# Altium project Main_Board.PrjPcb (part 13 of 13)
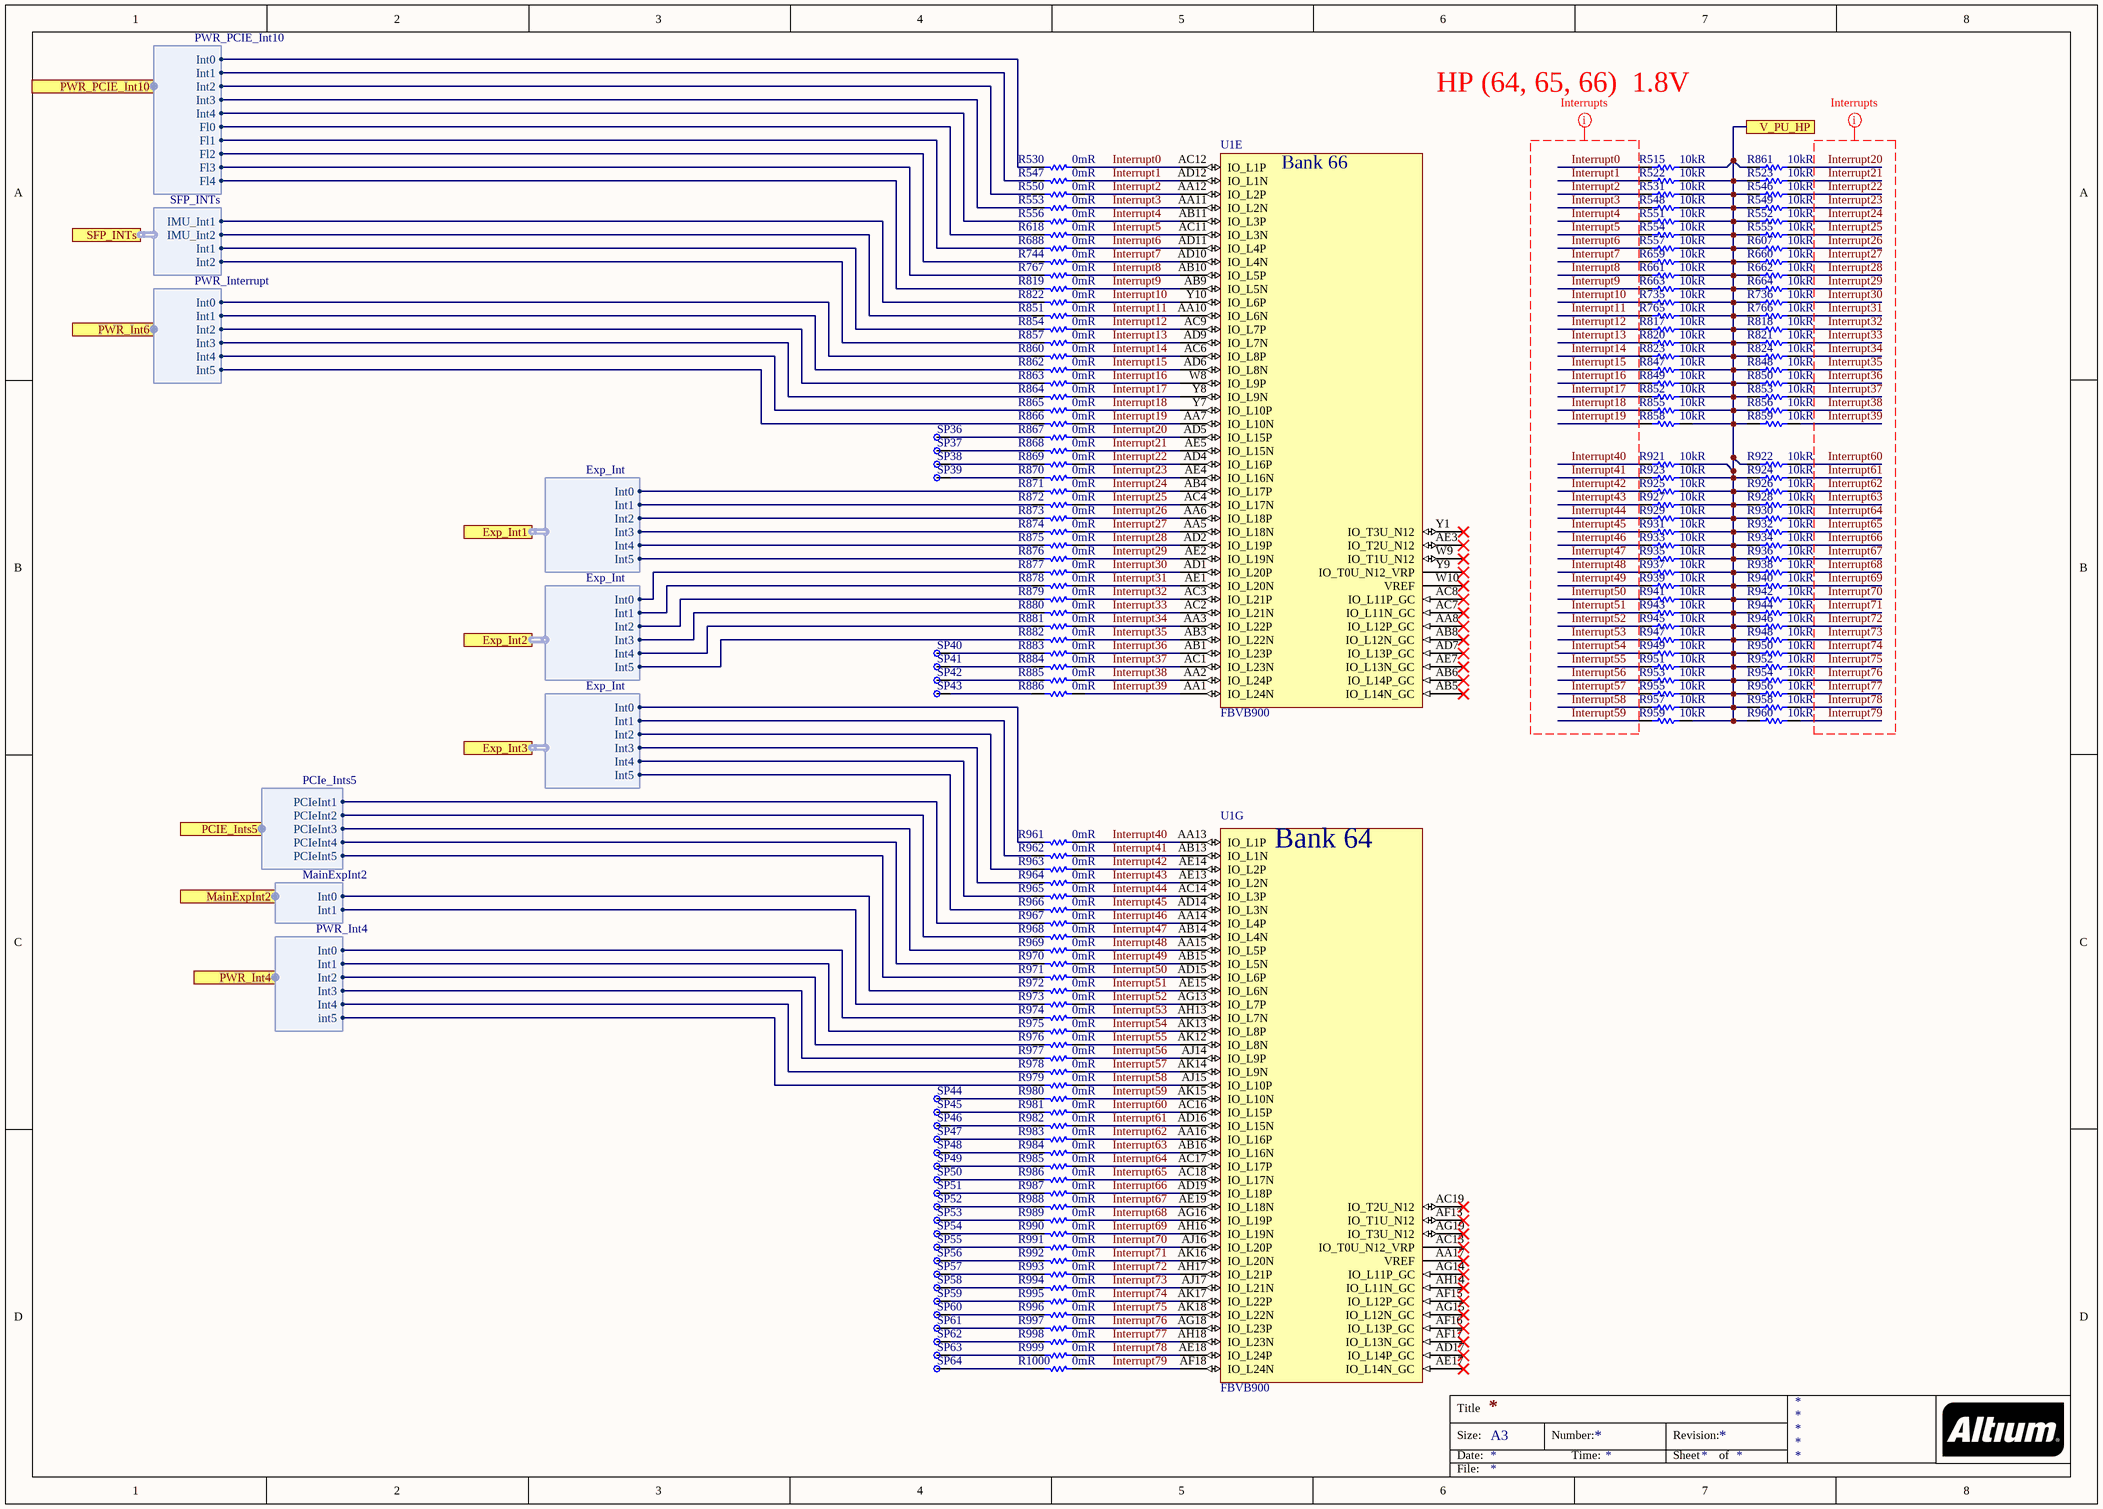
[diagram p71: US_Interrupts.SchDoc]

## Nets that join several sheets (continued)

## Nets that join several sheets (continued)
NetR760_2: Expander_RESET (R760.2 R761.1), U_Expander_RESET/I2C_Expander_Main_Rst (U35_I2C_Expander_Main_Rst.12)
NetR762_2: Expander_RESET (R762.2 R763.1), U_Expander_RESET/I2C_Expander_Main_Rst (U35_I2C_Expander_Main_Rst.11)
NetR860_2: PowerDistribition/HiCurrent/U_Pomiar_pradu_napiecia_3 (U64_U_Pomiar_pradu_napiecia_3.3), US_Interrupts (R860.2)
NetR862_2: PowerDistribition/HiCurrent/U_Pomiar_pradu_napiecia_4 (U64_U_Pomiar_pradu_napiecia_4.3), US_Interrupts (R862.2)
NetR863_2: PowerDistribition/HiCurrent/U_Pomiar_pradu_napiecia_5 (U64_U_Pomiar_pradu_napiecia_5.3), US_Interrupts (R863.2)
NetR864_2: PowerDistribition/HiCurrent/U_Pomiar_pradu_napiecia_6 (U64_U_Pomiar_pradu_napiecia_6.3), US_Interrupts (R864.2)
NetR865_2: Power_Hi_Curr (U18.A3), US_Interrupts (R865.2)
NetR866_2: Pomiar_napiecia_high_curr (U72.3), US_Interrupts (R866.2)
NetR918_2: Ultrascale+_02 (R918.2), Trans_LS_I2C0 (U36_Trans_LS_I2C0.8)
NetR919_2: Ultrascale+_02 (R919.2), Trans_LS_I2C1 (U36_Trans_LS_I2C1.8)
NetSP12_I2C_Bridge_GPIO_1: Ext_GPIO/I2C_Bridge_GPIO (SP12_I2C_Bridge_GPIO.1 U3_I2C_Bridge_GPIO.24), U_Expander_RESET/I2C_Expander_Main_Rst (U35_I2C_Expander_Main_Rst.3)
NetU24_SPI_bridge_Main_12: HighSpeed/SPI_bridge_PCIe (5 pins), SPI_bridge_Main (U24_SPI_bridge_Main.12)
NetU24_SPI_bridge_Main_13: HighSpeed/SPI_bridge_PCIe (5 pins), SPI_bridge_Main (U24_SPI_bridge_Main.13)
NetU24_SPI_bridge_Main_14: HighSpeed/SPI_bridge_PCIe (5 pins), SPI_bridge_Main (U24_SPI_bridge_Main.14)
NVMe_Rx_0_N: Sata (J27.47 R541.2), GTR (C677.2)
NVMe_Rx_0_P: Sata (J27.49 R541.1), GTR (C653.2)
NVMe_Rx_1_N: Sata (J27.35 R542.1), GTR (C716.2)
NVMe_Rx_1_P: Sata (J27.37 R542.2), GTR (C715.2)
NVMe_Tx_0_N: Sata (J27.41), GTR (C651.2)
NVMe_Tx_0_P: Sata (J27.43), GTR (C649.2)
NVMe_Tx_1_N: Sata (J27.29), GTR (C718.2)
NVMe_Tx_1_P: Sata (J27.31), GTR (C717.2)
OSC_500Out: System_CLK (TP20.1), DAC (X2.10), CLK_Mux (C333.1)
P4HS_PowerAlert_Pcie0: HighSpeed/Power4HighSpeed/U_Pomiar_pradu_napiecia_PCIe0 (U64_U_Pomiar_pradu_napiecia_PCIe0.3), US_Interrupts (R530.2)
P4HS_PowerAlert_Pcie1: HighSpeed/Power4HighSpeed/U_Pomiar_pradu_napiecia_PCIe1 (U64_U_Pomiar_pradu_napiecia_PCIe1.3), US_Interrupts (R547.2)
P4HS_PowerAlert_Pcie2: HighSpeed/Power4HighSpeed/U_Pomiar_pradu_napiecia_PCIe2 (U64_U_Pomiar_pradu_napiecia_PCIe2.3), US_Interrupts (R550.2)
P4HS_PowerAlert_Pcie3: HighSpeed/Power4HighSpeed/U_Pomiar_pradu_napiecia_PCIe3 (U64_U_Pomiar_pradu_napiecia_PCIe3.3), US_Interrupts (R553.2)
P4HS_PowerAlert_Pcie4: HighSpeed/Power4HighSpeed/U_Pomiar_pradu_napiecia_PCIe4 (U64_U_Pomiar_pradu_napiecia_PCIe4.3), US_Interrupts (R556.2)
PCIe_RESET: Ultrascale+_01 (R788.1 TP35.1), Sata (J27.50)
PG1_1: Power_Distribution (R835.1), Power_ADP1850_Dual (R295.2 U37.27)
PG1_2: Power_Distribution (R838.1), Power_ADP1850_Dual_1 (R313.2 U38.27)
PG1_TPS7A8801: TPS7A88_5V_Dual_3.3V_3.3V (R440.2 U61.17), PowerDistribition/Zasilanie CLK/I2C_Expander_PWR_CLK (U35_I2C_Expander_PWR_CLK.28)
PG2_2: Power_Distribution (R836.1), Power_ADP1850_Dual_1 (R314.2 U38.14)
PG2_TPS7A8801: TPS7A88_5V_Dual_3.3V_3.3V (R441.2 U61.9), PowerDistribition/Zasilanie CLK/I2C_Expander_PWR_CLK (U35_I2C_Expander_PWR_CLK.1)
PG2_TPS7A8801_0V9: Power_ADP1850_Dual (U37.8), TPS7A88_3V3_1V8_0V9V@2x1A (R676.2 U70.9), ST1L08_5V_0V6 (U73.5), Power_LED (T33.1)
PG_2V5@1.5A: Power_Hi_Curr (U18.A2), Power_Ethernet (R392.1 U49.5), Power_LED (T38.1)
PG_3V3@14A_EXP: Power_Distribution (R835.2 R837.1), PowerDistribition/I2C_Expander_PWR_Dist (U35_I2C_Expander_PWR_Dist.25), Power_LED (T37.1)
PG_5V@10A_EXP: Power_Distribution (R836.2 R839.1), PowerDistribition/I2C_Expander_PWR_Dist (U35_I2C_Expander_PWR_Dist.26), Power_LED (T41.1)
PG_12@8A_EXP: Power_Distribution (R838.2 R840.1), PowerDistribition/I2C_Expander_PWR_Dist (U35_I2C_Expander_PWR_Dist.27), Power_LED (T45.1)
PG_48_20V: PowerDistribition/I2C_Expander_PWR_Dist (U35_I2C_Expander_PWR_Dist.4), Power_48_20V@3A (U65.19), Power_LED (T49.1), GPIO_I2C (R828.2)
PG_ADP1850_1V2_REG4: ADP1741_3V3_0V85 (R435.1 R668.1 U69.4), Power_LED (T40.1)
PG_LT3042: LT3042_12V_5V_LNLDO (R442.1 U62.4), PowerDistribition/Zasilanie CLK/I2C_Expander_PWR_CLK (U35_I2C_Expander_PWR_CLK.25), Power_LED (R1082.1)
PG_PS_LTC6952_1: PowerDistribition/Zasilanie CLK/5to3V3_1 (R431_5to3V3_1.1 U59_5to3V3_1.5), PowerDistribition/Zasilanie CLK/I2C_Expander_PWR_CLK (U35_I2C_Expander_PWR_CLK.17), Power_LED (T32.1)
PG_PS_LTC6952_2: PowerDistribition/Zasilanie CLK/5to3V3_2 (R431_5to3V3_2.1 U59_5to3V3_2.5), PowerDistribition/Zasilanie CLK/I2C_Expander_PWR_CLK (U35_I2C_Expander_PWR_CLK.21), Power_LED (T47.1)
PGND: Power_48_20V@3A (17 pins), RJ45 (D3.2 D4.2 R324.1)
Power1_In: Power_Distribution (P8.1), PowerDistribition/U_Pomiar_pradu_napiecia_1 (R448_U_Pomiar_pradu_napiecia_1.1 U64_U_Pomiar_pradu_napiecia_1.10)
Power1_In_CM: Power_Switch (9 pins), PowerDistribition/U_Pomiar_pradu_napiecia_1 (R448_U_Pomiar_pradu_napiecia_1.2 U64_U_Pomiar_pradu_napiecia_1.8 U64_U_Pomiar_pradu_napiecia_1.9)
Power2_In: Power_Distribution (P10.1), PowerDistribition/U_Pomiar_pradu_napiecia_2 (R448_U_Pomiar_pradu_napiecia_2.1 U64_U_Pomiar_pradu_napiecia_2.10)
Power2_In_CM: Power_Switch (9 pins), PowerDistribition/U_Pomiar_pradu_napiecia_2 (R448_U_Pomiar_pradu_napiecia_2.2 U64_U_Pomiar_pradu_napiecia_2.8 U64_U_Pomiar_pradu_napiecia_2.9)
Power_3.3_1: Zasilanie_CLKDistribution (20 pins), TPS7A88_5V_Dual_3.3V_3.3V (6 pins)
Power_3.3_2: Zasilanie_CLKDistribution (10 pins), TPS7A88_5V_Dual_3.3V_3.3V (6 pins)
Power_MUX_Status0: Power_Switch (R630.2 U5.9), PowerDistribition/I2C_Expander_PWR_Dist (U35_I2C_Expander_PWR_Dist.22)
Power_MUX_Status1: Power_Switch (R11.1 U4.9), PowerDistribition/I2C_Expander_PWR_Dist (U35_I2C_Expander_PWR_Dist.23)
Power_MUX_Status2: Power_Switch (R13.2 U48.9), PowerDistribition/I2C_Expander_PWR_Dist (U35_I2C_Expander_PWR_Dist.24)
PS_MODE1: PS_Config (P2.3 R350.1 S1.2 U1.R19), USB3 (U74.2)
PS_POR: PS_Config (P3.2 R355.2 U1.N19), RJ45 (U76.1), FTDI (U77.6), USB3 (U74.1)
PS_Reset: PS_Config (P4.1 R354.1 U1.P20), FTDI (U77.4 U78.6)
PWR_ExtIO_INT0: PowerDistribition/I2C_Expander_PWR_Dist (U35_I2C_Expander_PWR_Dist.16), US_Interrupts (R977.2)
PWR_ExtIO_INT1: PowerDistribition/I2C_Expander_PWR_Dist (U35_I2C_Expander_PWR_Dist.15), US_Interrupts (R976.2)
PWR_ExtIO_INT2: PowerDistribition/Zasilanie CLK/I2C_Expander_PWR_CLK (U35_I2C_Expander_PWR_CLK.15), US_Interrupts (R978.2)
PWR_ExtIO_INT3: PowerDistribition/Zasilanie CLK/I2C_Expander_PWR_CLK (U35_I2C_Expander_PWR_CLK.16), US_Interrupts (R979.2)
PWR_ExtIO_nReset: PowerDistribition/I2C_Expander_PWR_Dist (U35_I2C_Expander_PWR_Dist.14), Expander_RESET (R755.1), U_Expander_RESET/I2C_Expander_Main_Rst (U35_I2C_Expander_Main_Rst.27)
PWR_OUT_20V: Power_Switch (18 pins), Power_Hi_Curr (R266.2), HI_Curr_ADP1850 (29 pins), Power_ADP1850_Dual (21 pins), Power_ADP1850_Dual_1 (21 pins)
PWR_PowerAlert0: PowerDistribition/I2C_Expander_PWR_Dist (U35_I2C_Expander_PWR_Dist.17), PowerDistribition/U_Pomiar_pradu_napiecia_1 (U64_U_Pomiar_pradu_napiecia_1.3), US_Interrupts (R974.2)
PWR_PowerAlert1: PowerDistribition/I2C_Expander_PWR_Dist (U35_I2C_Expander_PWR_Dist.18), PowerDistribition/U_Pomiar_pradu_napiecia_2 (U64_U_Pomiar_pradu_napiecia_2.3), US_Interrupts (R975.2)
PWR_Switch1_En: Power_Switch (U6.A2), PowerDistribition/I2C_Expander_PWR_Dist (U35_I2C_Expander_PWR_Dist.28)
PWR_Switch1_Flag: Power_Switch (R29.1 U6.A3), PowerDistribition/I2C_Expander_PWR_Dist (U35_I2C_Expander_PWR_Dist.1)
PWR_Switch2_En: Power_Switch (U7.A2), PowerDistribition/I2C_Expander_PWR_Dist (U35_I2C_Expander_PWR_Dist.2)
PWR_Switch2_Flag: Power_Switch (R30.1 U7.A3), PowerDistribition/I2C_Expander_PWR_Dist (U35_I2C_Expander_PWR_Dist.3)
RAM_DDR4_VTT: RAM (25 pins), ST1L08_5V_0V6 (C722.2 C723.2 R689.1 U73.8)
RAM_Vcc1V2: Power_ADP1850_Dual (R297.1), PowerDistribition/HiCurrent/U_Pomiar_pradu_napiecia_4 (R448_U_Pomiar_pradu_napiecia_4.2 U64_U_Pomiar_pradu_napiecia_4.8 U64_U_Pomiar_pradu_napiecia_4.9), RAM_Power (128 pins), XilinxPower (16 pins), FPGA_Decoupling (C741.2 C760.1 C761.2), RAM (C36.2 R58.2)
RF_SYSREF_TO_FPGA_N: Ultrascale+_02 (U1.AK11), HighSpeed/PCIE0 (J1_PCIE0.48)
RF_SYSREF_TO_FPGA_N: Ultrascale+_02 (U1.AG10), HighSpeed/PCIE1 (J1_PCIE1.48)
RF_SYSREF_TO_FPGA_N: Ultrascale+_02 (U1.AH9), HighSpeed/PCIE2 (J1_PCIE2.48)
RF_SYSREF_TO_FPGA_N: Ultrascale+_02 (U1.AE9), HighSpeed/PCIE3 (J1_PCIE3.48)
RF_SYSREF_TO_FPGA_N: Ultrascale+_02 (U1.AK5), HighSpeed/PCIE4 (J1_PCIE4.48)
RF_SYSREF_TO_FPGA_P: Ultrascale+_02 (U1.AJ11), HighSpeed/PCIE0 (J1_PCIE0.50)
RF_SYSREF_TO_FPGA_P: Ultrascale+_02 (U1.AF10), HighSpeed/PCIE1 (J1_PCIE1.50)
RF_SYSREF_TO_FPGA_P: Ultrascale+_02 (U1.AJ9), HighSpeed/PCIE2 (J1_PCIE2.50)
RF_SYSREF_TO_FPGA_P: Ultrascale+_02 (U1.AE8), HighSpeed/PCIE3 (J1_PCIE3.50)
RF_SYSREF_TO_FPGA_P: Ultrascale+_02 (U1.AJ5), HighSpeed/PCIE4 (J1_PCIE4.50)
RST_brigde: SFP_Group+IMU/I2C_Bridge_SFP (SP12_I2C_Bridge_SFP.1 U3_I2C_Bridge_SFP.24), Expander_RESET (R757.1), U_Expander_RESET/I2C_Expander_Main_Rst (U35_I2C_Expander_Main_Rst.1)
SetClk_Si53323_2: CLK_Mux (T36.1), Ultrascale+_02 (R900.2)
SFP0_LOS: SFP (J32.8 R66.1), SFP_Group+IMU/I2C_Expander_SFP (U35_I2C_Expander_SFP.4)
SFP0_Rx_N: SFP (J32.19), bank226 (C57#2.2 R706#2.2)
SFP0_Rx_P: SFP (J32.18), bank226 (C57#2.1 R705#2.2)
SFP0_Tx_N: SFP (J32.12), bank226 (C42.2 R704#2.2)
SFP0_Tx_P: SFP (J32.13), bank226 (C42.1 R703#2.2)
SFP0_TxDis: SFP (J32.3 R68.1), SFP_Group+IMU/I2C_Expander_SFP (U35_I2C_Expander_SFP.3)
SFP0_TxF: SFP (J32.2 R67.1), SFP_Group+IMU/I2C_Expander_SFP (U35_I2C_Expander_SFP.2)
SFP1_LOS: SFP1 (J33.8 R136.1), SFP_Group+IMU/I2C_Expander_SFP (U35_I2C_Expander_SFP.24)
SFP1_Rx_N: SFP1 (J33.19), bank226 (C68#2.2 R830#2.2)
SFP1_Rx_P: SFP1 (J33.18), bank226 (C68#2.1 R829#2.2)
SFP1_Tx_N: SFP1 (J33.12), bank226 (C58#2.2 R708#2.2)
SFP1_Tx_P: SFP1 (J33.13), bank226 (C58#2.1 R707#2.2)
SFP1_TxDis: SFP1 (J33.3 R138.1), SFP_Group+IMU/I2C_Expander_SFP (U35_I2C_Expander_SFP.23)
SFP1_TxF: SFP1 (J33.2 R137.1), SFP_Group+IMU/I2C_Expander_SFP (U35_I2C_Expander_SFP.22)
SFP2_LOS: SFP2 (J34.8 R146.1), SFP_Group+IMU/I2C_Expander_SFP (U35_I2C_Expander_SFP.27)
SFP2_Rx_N: SFP2 (J34.19), bank226 (C113#2.2 R834#2.2)
SFP2_Rx_P: SFP2 (J34.18), bank226 (C113#2.1 R833#2.2)
SFP2_Tx_N: SFP2 (J34.12), bank226 (C69#2.2 R832#2.2)
SFP2_Tx_P: SFP2 (J34.13), bank226 (C69#2.1 R831#2.2)
SFP2_TxDis: SFP2 (J34.3 R148.1), SFP_Group+IMU/I2C_Expander_SFP (U35_I2C_Expander_SFP.26)
SFP2_TxF: SFP2 (J34.2 R147.1), SFP_Group+IMU/I2C_Expander_SFP (U35_I2C_Expander_SFP.25)
SFP3_LOS: SFP3 (J35.8 R156.1), SFP_Group+IMU/I2C_Expander_SFP (U35_I2C_Expander_SFP.19)
SFP3_Rx_N: SFP3 (J35.19), bank226 (C117#2.2 R844#2.2)
SFP3_Rx_P: SFP3 (J35.18), bank226 (C117#2.1 R843#2.2)
SFP3_Tx_N: SFP3 (J35.12), bank226 (C114#2.2 R842#2.2)
SFP3_Tx_P: SFP3 (J35.13), bank226 (C114#2.1 R841#2.2)
SFP3_TxDis: SFP3 (J35.3 R158.1), SFP_Group+IMU/I2C_Expander_SFP (U35_I2C_Expander_SFP.18)
SFP3_TxF: SFP3 (J35.2 R157.1), SFP_Group+IMU/I2C_Expander_SFP (U35_I2C_Expander_SFP.17)
SFP_I2C4.SCL: WR_Clock (R130.2), SFP_Group+IMU/I2C_Bridge_SFP (R9_I2C_Bridge_SFP.2 SP11_I2C_Bridge_SFP.1 U3_I2C_Bridge_SFP.11), IMU (U58.13)
SFP_I2C4.SDA: WR_Clock (R131.2), SFP_Group+IMU/I2C_Bridge_SFP (R10_I2C_Bridge_SFP.2 SP10_I2C_Bridge_SFP.1 U3_I2C_Bridge_SFP.10), IMU (U58.14)
SFP_I2C5.SCL: Power_Distribution (R457.2 R465.2 R593.2 R597.2), Power_Hi_Curr (10 pins), PowerDistribition/HiCurrent/U_Pomiar_pradu_napiecia_3 (U64_U_Pomiar_pradu_napiecia_3.5), PowerDistribition/HiCurrent/U_Pomiar_pradu_napiecia_4 (U64_U_Pomiar_pradu_napiecia_4.5), PowerDistribition/HiCurrent/U_Pomiar_pradu_napiecia_5 (U64_U_Pomiar_pradu_napiecia_5.5), PowerDistribition/HiCurrent/U_Pomiar_pradu_napiecia_6 (U64_U_Pomiar_pradu_napiecia_6.5), Pomiar_napiecia_high_curr (U72.5), PowerDistribition/Zasilanie CLK/I2C_Expander_PWR_CLK (U35_I2C_Expander_PWR_CLK.8), PowerDistribition/I2C_Expander_PWR_Dist (U35_I2C_Expander_PWR_Dist.8), PowerDistribition/U_Pomiar_pradu_napiecia_1 (U64_U_Pomiar_pradu_napiecia_1.5), PowerDistribition/U_Pomiar_pradu_napiecia_2 (U64_U_Pomiar_pradu_napiecia_2.5), SFP_Group+IMU/I2C_Bridge_SFP (R7_I2C_Bridge_SFP.2 SP14_I2C_Bridge_SFP.1 U3_I2C_Bridge_SFP.13)
SFP_I2C5.SDA: Power_Distribution (R459.2 R466.2 R594.2 R598.2), Power_Hi_Curr (10 pins), PowerDistribition/HiCurrent/U_Pomiar_pradu_napiecia_3 (U64_U_Pomiar_pradu_napiecia_3.4), PowerDistribition/HiCurrent/U_Pomiar_pradu_napiecia_4 (U64_U_Pomiar_pradu_napiecia_4.4), PowerDistribition/HiCurrent/U_Pomiar_pradu_napiecia_5 (U64_U_Pomiar_pradu_napiecia_5.4), PowerDistribition/HiCurrent/U_Pomiar_pradu_napiecia_6 (U64_U_Pomiar_pradu_napiecia_6.4), Pomiar_napiecia_high_curr (U72.4), PowerDistribition/Zasilanie CLK/I2C_Expander_PWR_CLK (U35_I2C_Expander_PWR_CLK.9), PowerDistribition/I2C_Expander_PWR_Dist (U35_I2C_Expander_PWR_Dist.9), PowerDistribition/U_Pomiar_pradu_napiecia_1 (U64_U_Pomiar_pradu_napiecia_1.4), PowerDistribition/U_Pomiar_pradu_napiecia_2 (U64_U_Pomiar_pradu_napiecia_2.4), SFP_Group+IMU/I2C_Bridge_SFP (R8_I2C_Bridge_SFP.2 SP13_I2C_Bridge_SFP.1 U3_I2C_Bridge_SFP.12)
SFP_I2C6.SCL: HighSpeed/I2C_Bridge_PCIE (U3_I2C_Bridge_PCIE.19), SFP_Group+IMU/I2C_Bridge_SFP (R5_I2C_Bridge_SFP.2 SP16_I2C_Bridge_SFP.1 U3_I2C_Bridge_SFP.15)
SFP_I2C6.SDA: HighSpeed/I2C_Bridge_PCIE (U3_I2C_Bridge_PCIE.20), SFP_Group+IMU/I2C_Bridge_SFP (R6_I2C_Bridge_SFP.2 SP15_I2C_Bridge_SFP.1 U3_I2C_Bridge_SFP.14)
SFP_I2C7.SCL: SFP_Group+IMU/I2C_Bridge_SFP (R3_I2C_Bridge_SFP.2 SP18_I2C_Bridge_SFP.1 U3_I2C_Bridge_SFP.17), SFP_Group+IMU/I2C_Expander_SFP (U35_I2C_Expander_SFP.8)
SFP_I2C7.SDA: SFP_Group+IMU/I2C_Bridge_SFP (R4_I2C_Bridge_SFP.2 SP17_I2C_Bridge_SFP.1 U3_I2C_Bridge_SFP.16), SFP_Group+IMU/I2C_Expander_SFP (U35_I2C_Expander_SFP.9)
SFP_INT0: SFP_Group+IMU/I2C_Expander_SFP (U35_I2C_Expander_SFP.16), US_Interrupts (R854.2)
SFP_INT1: SFP_Group+IMU/I2C_Expander_SFP (U35_I2C_Expander_SFP.15), US_Interrupts (R857.2)
SFP_IO_nReset: SFP_Group+IMU/I2C_Expander_SFP (U35_I2C_Expander_SFP.14), Expander_RESET (R756.1), U_Expander_RESET/I2C_Expander_Main_Rst (U35_I2C_Expander_Main_Rst.28)
SGMI_C_Rx_N: RJ45 (C484.2), GTR (U1.G26)
SGMI_C_Rx_P: RJ45 (C483.2), GTR (U1.G25)
SGMI_C_Tx_N: RJ45 (C482.2), GTR (U1.G29)
SGMI_C_Tx_P: RJ45 (C479.2), GTR (U1.G30)
Si53323_1_Q2_LVDS_N: CLK_Mux (C725.1 R386.2 R387.2), Ultrascale+_02 (U1.AG3)
Si53323_1_Q2_LVDS_P: CLK_Mux (C724.1 R100.2 R125.2), Ultrascale+_02 (U1.AG4)
Si53323_2_Q1_N: CLK_Mux (U32.10), LTC6952 (C44.2 R79.2)
Si53323_2_Q1_P: CLK_Mux (U32.9), LTC6952 (C43.2 R76.1)
Si53323_2_Q2_LVDS_N: CLK_Mux (C727.1 R486.2 R487.2), Ultrascale+_02 (U1.A16)
Si53323_2_Q2_LVDS_P: CLK_Mux (C726.1 R427.2 R538.2), Ultrascale+_02 (U1.A17)
SPI1_CLK: Ultrascale+_01 (J25.1 R803.1), Ultrascale+_02 (U15.14), SPI_bridge_Main (5 pins)
SPI1_CS: Ultrascale+_01 (J25.4 R123.1 R806.1), Ultrascale+_02 (R124.1 U15.11), SPI_bridge_Main (5 pins)
SPI1_MISO: Ultrascale+_01 (J25.3 R807.1), Ultrascale+_02 (U15.13), SPI_bridge_Main (5 pins)
SPI1_MOSI: Ultrascale+_01 (J25.2 R808.1), Ultrascale+_02 (U15.12), SPI_bridge_Main (5 pins)
SPI_DAC_CS: DAC (U30.14), SPI_bridge_Main (R238_SPI_bridge_Main.1 SP27_SPI_bridge_Main.1 U27_SPI_bridge_Main.11)
SYNC_N: Ultrascale+_02 (U1.AK10), HighSpeed/PCIE0 (J1_PCIE0.12)
SYNC_N: Ultrascale+_02 (U1.AK8), HighSpeed/PCIE1 (J1_PCIE1.12)
SYNC_N: Ultrascale+_02 (U1.AF7), HighSpeed/PCIE2 (J1_PCIE2.12)
SYNC_N: Ultrascale+_02 (U1.AK6), HighSpeed/PCIE3 (J1_PCIE3.12)
SYNC_N: Ultrascale+_02 (U1.AK4), HighSpeed/PCIE4 (J1_PCIE4.12)
SYNC_P: Ultrascale+_02 (U1.AJ10), HighSpeed/PCIE0 (J1_PCIE0.14)
SYNC_P: Ultrascale+_02 (U1.AK9), HighSpeed/PCIE1 (J1_PCIE1.14)
SYNC_P: Ultrascale+_02 (U1.AF8), HighSpeed/PCIE2 (J1_PCIE2.14)
SYNC_P: Ultrascale+_02 (U1.AK7), HighSpeed/PCIE3 (J1_PCIE3.14)
SYNC_P: Ultrascale+_02 (U1.AJ4), HighSpeed/PCIE4 (J1_PCIE4.14)
uart0_RxD: Ultrascale+_01 (R779.1 TP32.1), FTDI (U57.12)
uart0_TxD: Ultrascale+_01 (R778.1 TP27.1), FTDI (U57.11)
uart1_RxD: Ultrascale+_01 (R776.1 TP31.1), FTDI (U57.13)
uart1_TxD: Ultrascale+_01 (R777.1 TP29.1), FTDI (U57.14)
US2_FTDI_UART1_RXD: Ultrascale+_02 (R910.2), FTDI (U79.13)
US2_FTDI_UART1_TXD: Ultrascale+_02 (R909.2), FTDI (U79.14)
US+_MGTVccAux: Ultrascale+_02 (7 pins), Power_Low_Curr (7 pins), XilinxPower (18 pins), FPGA_Decoupling (C756.2 C759.2), Trans_LS_I2C0 (U36_Trans_LS_I2C0.2), Trans_LS_I2C1 (U36_Trans_LS_I2C1.2), FTDI (U79.15), US_Interrupts (80 pins)
US+_Vcc_PS_Batt: XilinxPower (B1.1 R276.1 U1.U20), FPGA_Decoupling (C747.1 C748.2)
US+_Vcc_PS_DDR_504: Power_Low_Curr (9 pins), XilinxPower (7 pins), FPGA_Decoupling (C753.1 C754.2 C755.2)
US+_Vcc_PS_IntFp: HI_Curr_ADP1850 (R271.2), Pomiar_napiecia_high_curr (R617.2 U72.8 U72.9), XilinxPower (53 pins), FPGA_Decoupling (11 pins)
US_PS_JTAG_TCK: PS_Config (R346.2 U1.L19), FTDI (R1028.2)
US_PS_JTAG_TDI: PS_Config (R347.2 U1.L20), FTDI (R1026.2)
US_PS_JTAG_TDO: PS_Config (U1.M20), FTDI (R1029.2)
US_PS_JTAG_TMS: PS_Config (R348.2 U1.L21), FTDI (R1027.2)
USB2_CLK: Ultrascale+_01 (R362.2), USB3 (U45.1)
USB2_D0: Ultrascale+_01 (R116.2), USB3 (U45.3)
USB2_D1: Ultrascale+_01 (R117.2), USB3 (U45.4)
USB2_D2: Ultrascale+_01 (R115.2), USB3 (U45.5)
USB2_D3: Ultrascale+_01 (R119.2), USB3 (U45.6)
USB2_D4: Ultrascale+_01 (R120.2), USB3 (U45.7)
USB2_D5: Ultrascale+_01 (R121.2), USB3 (U45.9)
USB2_D6: Ultrascale+_01 (R122.2), USB3 (U45.10)
USB2_D7: Ultrascale+_01 (R802.1), USB3 (U45.13)
USB2_DIR: Ultrascale+_01 (R800.1), USB3 (U45.31)
USB2_NXT: Ultrascale+_01 (R801.1), USB3 (U45.2)
USB2_STP: Ultrascale+_01 (R118.2), USB3 (U45.29)
USB_RX_N: USB3 (C543.2), GTR (U1.J25)
USB_RX_P: USB3 (C542.2), GTR (U1.J26)
USB_TX_N: USB3 (C541.2), GTR (U1.H28)
USB_TX_P: USB3 (C540.2), GTR (U1.H27)
uSD_CD: Ultrascale+_01 (R782.1), uSD (R381.1 R845#2.2 U47.D3)
uSD_CLK: Ultrascale+_01 (R96.2 R97.1), uSD (U47.C1)
uSD_CMD: Ultrascale+_01 (R95.2), uSD (U47.D2)
uSD_D0: Ultrascale+_01 (R87.2), uSD (U47.D1)
uSD_D1: Ultrascale+_01 (R88.2), uSD (U47.E1)
uSD_D2: Ultrascale+_01 (R89.2), uSD (U47.A1)
uSD_D3: Ultrascale+_01 (R90.2), uSD (U47.B1)
uSD_D4: Ultrascale+_01 (R91.1), uSD (U47.B2)
uSD_D5: Ultrascale+_01 (R92.1), uSD (U47.A2)
uSD_D6: Ultrascale+_01 (R93.1), uSD (U47.A3)
uSD_D7: Ultrascale+_01 (R94.1), uSD (U47.E3)
V_PoE+: Power_48_20V@3A (6 pins), RJ45 (D3.1 D4.1 R324.2)
VDD_DIG: WR_Clock (7 pins), Zasilanie_CLKDistribution (C93.1 C165.2 FB21.2 U16.8)
Vout1_1: Power_ADP1850_Dual (13 pins), PowerDistribition/HiCurrent/U_Pomiar_pradu_napiecia_3 (R448_U_Pomiar_pradu_napiecia_3.1 U64_U_Pomiar_pradu_napiecia_3.10)
Vout1_2: Power_ADP1850_Dual_1 (13 pins), PowerDistribition/HiCurrent/U_Pomiar_pradu_napiecia_5 (R448_U_Pomiar_pradu_napiecia_5.1 U64_U_Pomiar_pradu_napiecia_5.10)
Vout2_1: Power_ADP1850_Dual (13 pins), PowerDistribition/HiCurrent/U_Pomiar_pradu_napiecia_4 (R448_U_Pomiar_pradu_napiecia_4.1 U64_U_Pomiar_pradu_napiecia_4.10)
Vout2_2: Power_ADP1850_Dual_1 (13 pins), PowerDistribition/HiCurrent/U_Pomiar_pradu_napiecia_6 (R448_U_Pomiar_pradu_napiecia_6.1 U64_U_Pomiar_pradu_napiecia_6.10)
WR_LMK_CLK_RC_HF1_N: WR_Clock (C729.2 R1086.1), Ultrascale+_02 (U1.AJ1)
WR_LMK_CLK_RC_HF1_P: WR_Clock (C729.1 R1085.1), Ultrascale+_02 (U1.AJ2)
WR_LMK_CLK_RC_HF2_N: WR_Clock (C730.2 R1088.1), Ultrascale+_02 (U1.C17)
WR_LMK_CLK_RC_HF2_P: WR_Clock (C730.1 R1087.1), Ultrascale+_02 (U1.B16)

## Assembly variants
wr_i2c: not fitted R132 R403 R405 R407 R408 R412 R414 R416 R418 R637 R638 R641 R642 R723 R724 R727 R728
Standard: not fitted C587 R14 R14 R14 R16 R16 R16 R22 R22 R22 R69 R70 R71 R72 R73 R74 R100 R125 R126 R127 R127 R128 R128 R129 R129 R132 R133 R134 R140 R141 R142 R143 R144 R144 R151 R152 R153 R154 R161 R162 R163 R164 R175 R175 R176 R176 R177 R177 R178 R178 R179 R179 R180 R180 R183 R183 R185 R185 R186 R186 R187 R187 R188 R188 R189 R189 R192 R192 R193 R193 R194 R194 R196 R196 R197 R197 R198 R198 R201 R201 R202 R202 R204 R204 R205 R205 R206 R206 R207 R207 R211 R211 R213 R213 R215 R215 R217 R217 R219 R219 R222 R222 R230 R230 R242 R244 R246 R247 R248 R249 R250 R251 R256 R258 R259 R260 R261 R262 R264 R277 R278 R281 R281 R283 R286 R292 R294 R295 R296 R304 R304 R304 R312 R313 R314 R342 R343 R344 R344 R345 R345 R366 R366 R389 R389 R389 R390 R390 R390 R403 R405 R407 R408 R412 R414 R416 R418 R427 R446 R450 R451 R451 R453 R453 R456 R457 R457 R458 R458 R459 R459 R462 R462 R463 R463 R465 R465 R466 R466 R467 R467 R469 R469 R471 R471 R473 R473 R475 R475 R478 R479 R479 R492 R494 R494 R496 R497 R500 R501 R502 R504 R504 R508 R511 R512 R512 R516 R516 R518 R518 R520 R520 R525 R525 R526 R526 R528 R528 R538 R561 R561 R562 R562 R563 R563 R566 R566 R567 R567 R568 R568 R569 R569 R570 R570 R572 R572 R574 R574 R575 R575 R576 R576 R578 R578 R579 R579 R580 R580 R581 R581 R583 R583 R584 R584 R585 R585 R587 R587 R588 R588 R589 R589 R591 R591 R592 R592 R593 R593 R594 R594 R596 R596 R597 R597 R598 R598 R600 R629 R637 R638 R641 R642 R669 R696 R697 R697 R699 R700 R701 R701 R703 R706 R707 R723 R724 R727 R728 R738 R738 R740 R740 R742 R742 R758 R758 R760 R760 R763 U42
